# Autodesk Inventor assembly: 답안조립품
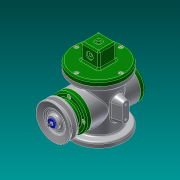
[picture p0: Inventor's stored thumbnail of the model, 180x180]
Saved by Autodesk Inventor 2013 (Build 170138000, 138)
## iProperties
Created: 2018-02
Part Number: 답안조립품
Document SubType Name: Assembly
Designer: Administrator
Author: Administrator
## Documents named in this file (18)
- C:\Users\Administrator\Desktop\480208V1014\답안조립품.iam
- C:\Users\Administrator\Desktop\480208V1014\본체.ipt
- C:\Users\Administrator\Desktop\480208V1014\E-링.ipt
- C:\Users\Administrator\Desktop\480208V1014\V-벨트풀리.ipt
- C:\Users\Administrator\Desktop\480208V1014\덮개.ipt
- C:\Users\Administrator\Desktop\480208V1014\뒤커버.ipt
- C:\Users\Administrator\Desktop\480208V1014\링크.ipt
- C:\Users\Administrator\Desktop\480208V1014\베어링 17 x 40 x 12.ipt
- C:\Users\Administrator\Desktop\480208V1014\볼트 M4 x 8.ipt
- C:\Users\Administrator\Desktop\480208V1014\볼트 M4 x 10.ipt
- C:\Users\Administrator\Desktop\480208V1014\슬라이더.ipt
- C:\Users\Administrator\Desktop\480208V1014\앞커버.ipt
- C:\Users\Administrator\Desktop\480208V1014\오일 실 17 30 8.ipt
- C:\Users\Administrator\Desktop\480208V1014\와셔 4x16.ipt
- C:\Users\Administrator\Desktop\480208V1014\클레비스 핀 6 x 22.ipt
- 클레비스 핀 6 x 22.ipt
- C:\Users\Administrator\Desktop\480208V1014\키 4 x 4 x 12.ipt
- C:\Users\Administrator\Desktop\480208V1014\편심축.ipt
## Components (2 placed, 2 different names)
1. E-링:1
2. V-벨트풀리:1 — 각도:1
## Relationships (1: Angle 1)
- 각도:1 [Angle]: V-벨트풀리:1
